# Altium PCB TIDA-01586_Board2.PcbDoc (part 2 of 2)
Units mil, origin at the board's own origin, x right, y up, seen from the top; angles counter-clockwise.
Board outline 2300 x 1600 mil, 4 copper layers (Layer 1 - Top Layer, Layer 2 - PWR, Layer 3 - GND, Layer 4 - Bottom Layer), stack 61.634 mil thick; 117 components, 50 nets, 280 pads, 152 vias.
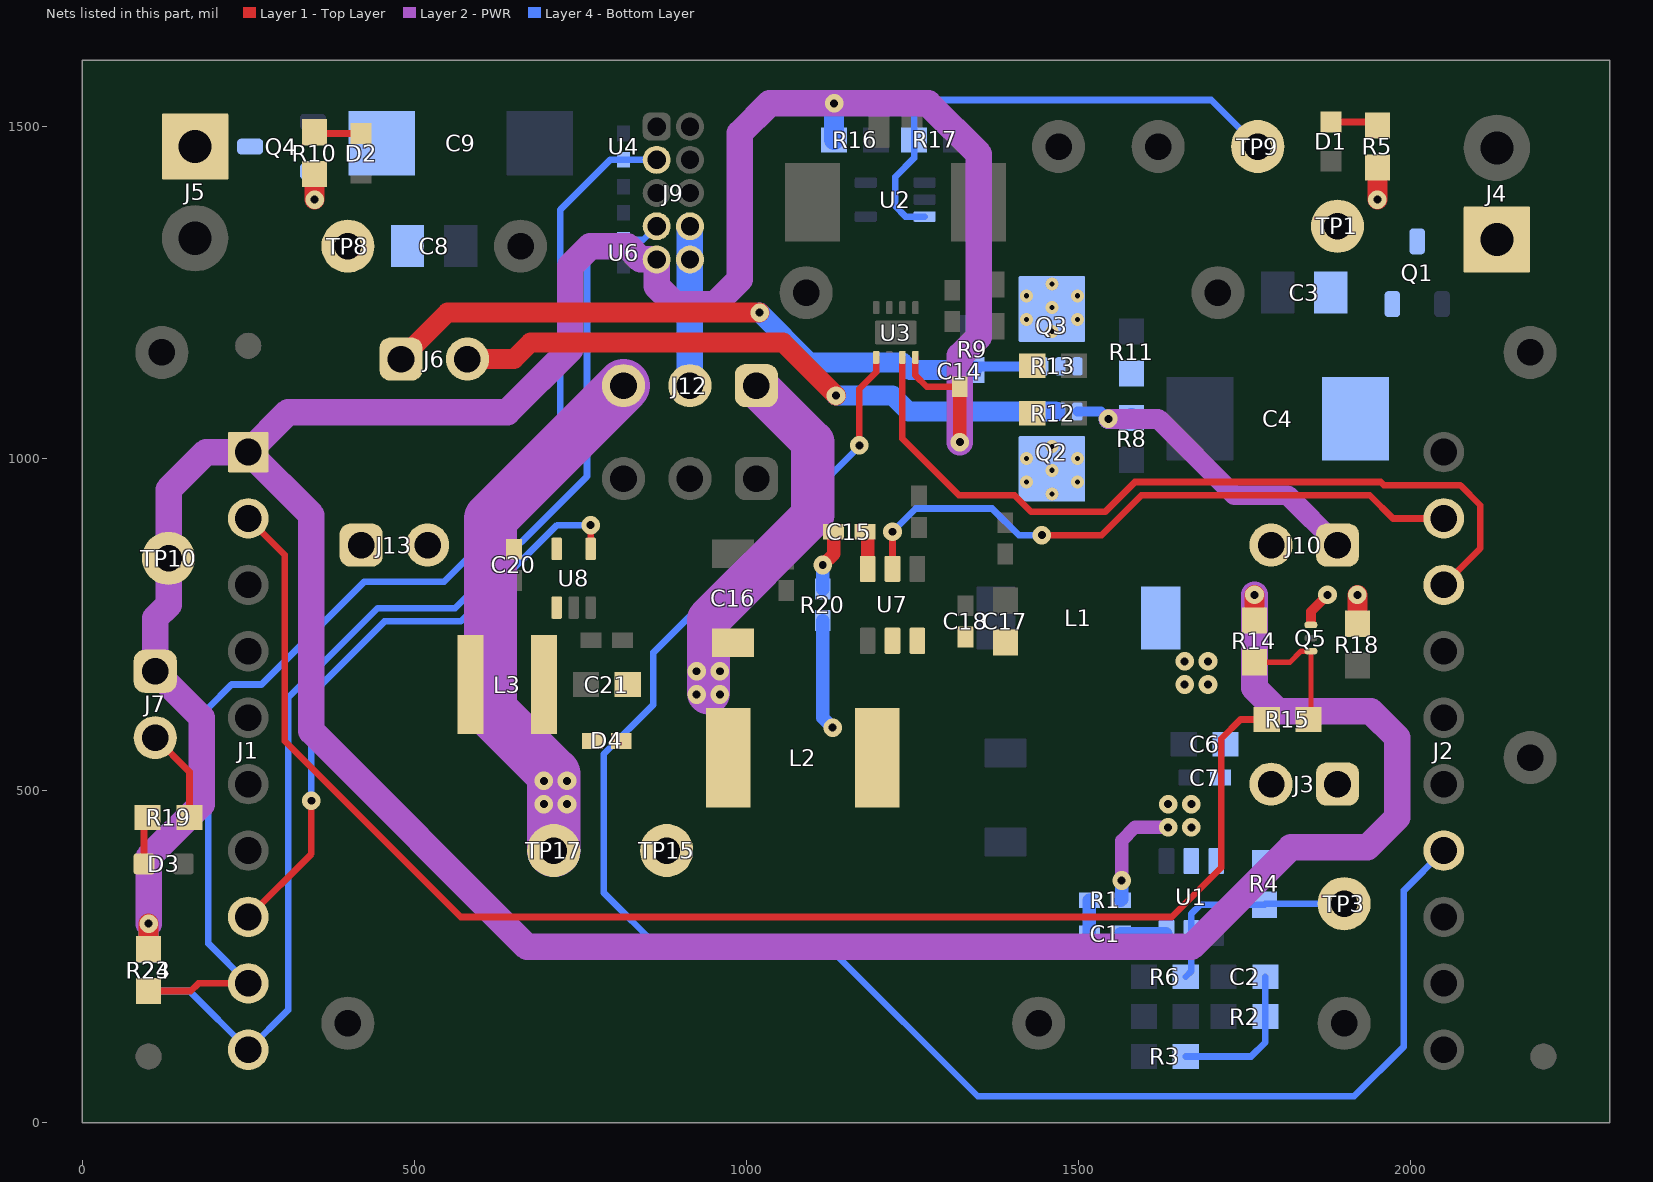
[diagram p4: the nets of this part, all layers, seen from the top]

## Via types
v1: diameter 28, hole 12, Layer 1 - Top Layer to Layer 4 - Bottom Layer, tented both sides, 136 vias
v2: diameter 19.68, hole 7.87, Layer 1 - Top Layer to Layer 4 - Bottom Layer, tented both sides, 16 vias

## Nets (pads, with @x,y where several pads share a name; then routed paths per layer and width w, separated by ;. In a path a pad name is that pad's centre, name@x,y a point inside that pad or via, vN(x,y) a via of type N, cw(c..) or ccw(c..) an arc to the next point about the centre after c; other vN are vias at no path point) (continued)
N12V_PRES: J1.2 R15.2 | length 2182.7
  Layer 1 - Top Layer w10: J1.2@250,910 305,855 305,575 570,310 1640.49,310 1715,384.51 1715,578.29 1743.94,607.24 R15.2@1783.5,607.24
N_SLEEP: J2.18 U3.7 | length 1214.1
  Layer 1 - Top Layer w10: U3.7@1234.84,1152.6 1234.84,1030.16 1320,945 1403.82,945 1428.82,920 1540,920 1585,965 1955,965 1960,960 2075,960 2105,930 2105,865 J2.18@2050,810
NetC1_1: C1.1 U1.6 | length 69.3
  Layer 4 - Bottom Layer w10: U1.6@1631.73,285 U1.6@1632.6,285.87
  Layer 4 - Bottom Layer w20: C1.1@1563.62,285 U1.6@1631.73,285
NetC1_2: C1.2 R1.1 | length 50
  Layer 4 - Bottom Layer w20: C1.2@1516.38,285 R1.1@1516.38,335
NetC2_1: C2.1 R2.1 R3.2 | length 227.4
  Layer 4 - Bottom Layer w10: R3.2@1661.5,100 1760,100 1781.5,121.5 R2.1@1781.5,160 C2.1@1781.5,220
NetC15_1: C15.1 U7.6 | length 57.5
  Layer 1 - Top Layer w20: C15.1@1178.62,890 1182.6,886.02 U7.6@1182.6,834.13
NetC15_2: C15.2 R20.1 | length 93.2
  Layer 1 - Top Layer w20: v1(1115,840) 1131.38,856.38 C15.2@1131.38,890
  Layer 4 - Bottom Layer w20: R20.1@1115,803.62 v1(1115,840)
NetD1_1: D1.1 R5.1 | length 72.2
  Layer 1 - Top Layer w10: D1.1@1880,1506.91 1944.59,1506.91 R5.1@1950,1501.5
NetD2_1: D2.1 R10.1 | length 70.8
  Layer 1 - Top Layer w10: R10.1@350,1491.5 351.97,1489.53 D2.1@420,1489.53
NetD3_1: D3.1 R19.1 | length 72.2
  Layer 1 - Top Layer w10: D3.1@93.09,390 93.09,454.59 R19.1@98.5,460
NetJ4_1: J4.1 Q1.3
NetJ5_1: J5.1 Q4.3
NetJ7_2: J7.2 R19.2 | length 141.3
  Layer 1 - Top Layer w10: J7.2@110,580 161.5,528.5 R19.2@161.5,460
NetQ2_5: Q2.5 Q2.6 Q2.7 Q2.8 Q2.9@1460,984.61 R12.1
  other v2: 1460,946.91 1421.61,964.72 1498.39,964.72 1460,982.54 1421.61,1000.35 1498.39,1000.35 1460,1018.17
NetQ3_1: Q3.1 Q3.2 Q3.3 R11.1
NetQ3_5: Q3.5 Q3.6 Q3.7 Q3.8 Q3.9@1460,1225.39 R13.2
  other v2: 1460,1191.83 1421.61,1209.65 1498.39,1209.65 1460,1227.46 1421.61,1245.28 1498.39,1245.28 1460,1263.09
NetQ5_3: Q5.3@1850,710.32 R14.1 R15.1 | length 196.5
  Layer 1 - Top Layer w8: R14.1@1765,693.5 1818.5,693.5 1835.32,710.32 Q5.3@1850,710.32 1850,610.74 R15.1@1846.5,607.24
NetR4_2: R4.2 R6.2 TP3.1 U1.5 | length 334.7
  Layer 4 - Bottom Layer w10: R6.2@1661.5,220 1670,228.5 U1.5@1670,285.87 1670,315 1683.5,328.5 R4.2@1780,328.5 1781.5,330 TP3.1@1900,330
NetR17_2: R17.2 TP9.1 U2.3 | length 755.8
  Layer 4 - Bottom Layer w10: U2.3@1268.39,1364.41 1239.69,1364.41 1224.09,1380 1224.09,1424.09 1252.6,1452.6 R17.2@1252.6,1480 1252.6,1517.6 1275,1540 1700,1540 TP9.1@1770,1470
OPEN_ICR: J2.14 U3.5 | length 2658.9
  Layer 1 - Top Layer w10: v1(1170,1020) 1170,1105 1195.47,1130.47 U3.5@1195.47,1152.6
  Layer 4 - Bottom Layer w10: v1(1170,1020) 1170,1018.28 860,708.28 860,630 785,555 785,346.72 871.72,260 1128.32,260 1348.32,40 1915,40 1990,115 1990,350 J2.14@2050,410
PWM_BOOST: J1.8 U8.4 | length 936.3
  Layer 1 - Top Layer w10: J1.8@250,310 345,405 v1(345,485) ; U8.4@765.59,864.29 v1(765.59,900)
  Layer 4 - Bottom Layer w10: v1(345,485) 345,645 455,755 570,755 715,900 v1(765.59,900)
PWM_BUCK: J2.19 U7.5 | length 956.3
  Layer 1 - Top Layer w10: U7.5@1220,834.13 v1(1220,890) ; v1(1445,885) 1535,885 1595,945 1938.62,945 1973.62,910 J2.19@2050,910
  Layer 4 - Bottom Layer w10: v1(1220,890) 1255,925 1370,925 1410,885 v1(1445,885)
SCL: J1.9 J9.3 R23.1 U4.1 | length 1851.7
  Layer 1 - Top Layer w10: R23.1@100,198.5 163.5,198.5 175,210 J1.9@250,210
  Layer 4 - Bottom Layer w10: J1.9@250,210 190,270 190,625 225,660 270,660 425,815 545,815 720,990 720,1375 795.32,1450.32 U4.1@815,1450.32 ; 800.32,1450 J9.3@865,1450
SDA: J1.10 J9.7 R24.1 U6.1 | length 1779
  Layer 4 - Bottom Layer w10: R24.1@100,198.5 161.5,198.5 J1.10@250,110 310,170 310,640 445,775 561.57,775 760,973.43 760,1295 794.68,1329.68 U6.1@815,1329.68 844.68,1329.68 J9.7@865,1350
sw_12v5v: L1.1 R1.2 U1.2 | length 168.9
  Layer 2 - PWR w20: v1(1565,365) 1565,425 1585,445 v1(1635,445)
  Layer 4 - Bottom Layer w20: R1.2@1563.62,335 1565,336.38 v1(1565,365)
  other v1: 1670,445 1635,480 1670,480 1660,660 1695,660 1660,695 1695,695
sw_led_boost: D4.2 L3.2 U8.1
sw_led_buck: L2.1 R20.2 U7.2 | length 167.6
  Layer 4 - Bottom Layer w20: R20.2@1115,756.38 1115,610 v1(1130,595)
VCC: J9.8 J9.10 J12.2 | length 240
  Layer 4 - Bottom Layer w40: J12.2@915,1110 J9.10@915,1300 J9.8@915,1350
VCC_3V: C14.1 J1.1 J7.1 J9.9 R14.2 R16.2 R23.2 R24.2 TP10.1 U3.8 | length 6130.6
  Layer 1 - Top Layer w10: U3.8@1254.53,1152.6 1254.53,1125.47 1271.67,1108.33 C14.1@1321.32,1108.33
  Layer 1 - Top Layer w20: v1(1321.32,1025) C14.1@1321.32,1108.33
  Layer 1 - Top Layer w30: R23.2@100,261.5 v1(100,300) ; R14.2@1765,756.5 v1(1765,795)
  Layer 2 - PWR w40: v1(100,300) 100,400 180,480 180,610 J7.1@110,680 110,760 130,780 TP10.1@130,850 130,953.5 186.5,1010 J1.1@250,1010 ; v1(1321.32,1025) 1321.32,1154.92 1350,1183.6 1350,1458.7 1273.7,1535 v1(1132.08,1535) 1035,1535 990,1490 990,1270 952.5,1232.5 892.5,1232.5 865,1260 J9.9@865,1300 840.9,1300 820.9,1320 765,1320 735,1290 735,1165 640,1070 310,1070 J1.1@250,1010 ; v1(1765,795) 1765,655 1800,620 1940,620 1980,580 1980,460 1935,415 1820,415 1670,265 670,265 345,590 345,915 J1.1@250,1010
  Layer 4 - Bottom Layer w30: R24.2@100,261.5 v1(100,300) ; R16.2@1132.08,1480 v1(1132.08,1535)
VIN_5V: C8.2 C9.1 J6.1 J13.1 Q3.4 Q4.2 R9.2 R10.2 TP8.1 | length 1047.2
  Layer 1 - Top Layer w30: v1(349.97,1390) R10.2@350,1428.5 ; J6.1@480,1150 550,1220 v1(1020,1220)
  Layer 4 - Bottom Layer w15: R9.2@1340,1133.5 1345.5,1139 1376,1139 Q3.4@1421.61,1138.98
  Layer 4 - Bottom Layer w30: v1(1020,1220) 1095,1145 1235,1145 1246.5,1133.5 R9.2@1340,1133.5
vin_5vor: J6.2 Q2.1 Q2.2 Q2.3 | length 938.4
  Layer 1 - Top Layer w30: J6.2@580,1150 650,1150 675,1175 1055,1175 v1(1135,1095)
  Layer 4 - Bottom Layer w30: v1(1135,1095) 1220,1095 1243.98,1071.02 Q2.1@1421.61,1071.02 Q2.3@1465,1071.02
VIN_12V: C3.1 C4.1 J3.1 J10.1 Q1.2 Q2.4 Q5.1@1850,749.68 R5.2 R8.2 R18.1 TP1.1 | length 654.9
  Layer 1 - Top Layer w15: Q5.1@1850,753 1850,770 v1(1875,795)
  Layer 1 - Top Layer w30: R18.1@1920,751.5 v1(1920,795) ; v1(1950,1390) R5.2@1950,1438.5
  Layer 2 - PWR w30: v1(1545,1060) 1620,1060 1735,945 1815,945 J10.1@1890,870
  Layer 4 - Bottom Layer w15: Q2.4@1498.39,1071.02 1533.98,1071.02 v1(1545,1060)
  Layer 4 - Bottom Layer w30: v1(1545,1060) 1578.5,1060 R8.2@1580,1061.5
vin_12v5v: C6.1 C7.1 J3.2 R4.1 U1.3
vin_led_boost: C20.1 J13.2 L3.1 U8.5
vin_led_buck: C17.1 C18.1 J10.2 U7.3
vled_top_boost: C21.1 D4.1 J12.3 TP17.1 | length 822.2
  Layer 2 - PWR w80: TP17.1@710,410 710,525 615,620 615,910 J12.3@815,1110
  other v1: 695,480 730,480 695,515 730,515
vled_top_buck: C16.1 J12.1 L2.2 TP15.1 | length 563.2
  Layer 2 - PWR w65: 943,647 943,758 1100,915 1100,1025 J12.1@1015,1110
  other v1: 925,645 960,645 925,680 960,680
pads on no net: D3. FID1.1 FID2.1 FID3.1 FID4.1 FID5.1 FID6.1 J1.3 J1.4 J1.6 J1.7 J2.11 J2.12 J2.13 J2.16 J2.17 J8.3 J8.4 Q2.9@1421.61,963.74 Q2.9@1433.92,982.54 Q2.9@1433.92,1018.17 Q2.9@1447.2,963.74 Q2.9@1460,997.11 Q2.9@1472.8,963.74 Q2.9@1486.08,982.54 Q2.9@1486.08,1018.17 Q2.9@1498.39,963.74 Q3.9@1421.61,1246.26 Q3.9@1433.92,1191.83 Q3.9@1433.92,1227.46 Q3.9@1447.2,1246.26 Q3.9@1460,1212.89 Q3.9@1472.8,1246.26 Q3.9@1486.08,1191.83 Q3.9@1486.08,1227.46 Q3.9@1498.39,1246.26 Q5.1@1850,750.67 Q5.2@1850,730 Q5.3@1850,709.33 SH-J3.0 SH-J6.0 SH-J7.0 SH-J10.0 SH-J11.0 SH-J12.0 SH-J13.0 U2.4 U3.9@1207.28,1190 U3.9@1242.72,1190

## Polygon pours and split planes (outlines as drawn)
GND on Layer 3 - GND "Layer 3 - GND - GND " (solid, remove dead copper, pour order 0): 20,20 2280,20 2280,1580 20,1580
GND on Layer 1 - Top Layer "Layer 1 - Top Layer - GND " (solid, remove dead copper, pour order 4): 20,20 2280,20 2280,1580 20,1580
GND on Layer 2 - PWR "Layer 2 - PWR - GND " (solid, remove dead copper, pour order 6): 20,20 2280,20 2280,1580 20,1580
GND on Layer 4 - Bottom Layer "Layer 4 - Bottom Layer - GND " (solid, remove dead copper, pour order 8): 20,20 2280,20 2280,1580 20,1580

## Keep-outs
Keep-Out Layer:
  text ".Layer_Name" at 577,-858.49 h60

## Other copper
Layer 1 - Top Layer:
  region net GND: 1201,1238 1201,1214 1207,1208 1283,1208 1298,1223 1385,1223 1389,1219 1389,1169 1359,1139 1301,1139 1268,1172 1163,1172 1150,1185 1150,1225 1163,1238
  region net fb_led_buck: 1075,832 1075,980 1050,1005 985,1005 965,985 965,935 935,905 935,832
  region net vled_top_boost: 795,680 795,615 795,550 780,535 695,535 650,490 650,380 665,365 775,365 795,385 795,425 885,515 885,660 865,680
  region net DRV_5V: 1249,1217 1277,1217 1295,1235 1385,1235 1390,1240 1390,1280 1385,1285 1305,1285 1275,1255 1258,1255 1249,1246
  region net NetQ3_5: 1455,1118.39 1455,1163.39 1475,1183.39 1500,1183.39 1510,1193.39 1510,1261.39 1496.39,1275 1435,1275 1410,1250 1410,1118.39
  region net NetQ2_5: 1455,1090 1455,1045 1475,1025 1500,1025 1510,1015 1510,947 1500,937 1435,937 1410,962 1410,1090
  region net vin_led_boost: 610,831 626,847 722,847 730,855 730,895 715,910 510,910 480,880 480,585 500,565 590,565 610,585
  region net GND: 660,795 670,805 721,805 732,794 732,618 745,605 767,605 784,622 784,738 778,744 756,744 748,752 748,819 733,834 635,834 630,829 630,800 635,795
  region net sw_led_boost: 737,590 723,604 723,791 721,793 688,793 650,755 650,590 685,555 782,555 785,558 785,587 782,590
  region net vled_top_buck: 1005,755 1020,740 1020,420 960,360 840,360 815,385 815,420 900,505 900,740 915,755
  region net sw_led_buck: 1233,745 1233,473 1205,445 1145,445 1115,475 1115,604.34 1207,696.34 1207,745 1212,750 1228,750
  region net GND: 1420,855 1400,875 1370,875 1345,900 1320,900 1285,865 1285,810 1275,800 1105,800 1085,820 1045,820 1035,810 1035,705 1050,690.22 1179.78,690.22 1194.57,705 1194.57,749.57 1207,762 1420,762
  region net vin_led_buck: 1825,850 1805,830 1660,830 1485,655 1275,655 1245,685 1245,745 1250,750 1435,750 1605,920 1805,920 1825,900
  pour cut-out: 1199.17,420.08 1222.8,443.7 1222.8,690.22 947.2,690.22 947.2,443.7 970.83,420.08
  pour cut-out: 618.35,577.32 661.65,577.32 661.65,742.68 618.35,742.68
  text ".Layer_Name" at 577,-858.49 h60
Layer 2 - PWR:
  region net sw_12v5v: 1620,485 1640,505 1640,620 1640,700 1650,710 1710,710 1720,700 1720,440 1705,425 1635,425 1620,440
  text ".Layer_Name" at 577,-858.49 h60
Layer 3 - GND:
  text ".Layer_Name" at 577,-858.49 h60
Layer 4 - Bottom Layer:
  region net vin_5vor: 1464,1086 1481,1086 1481,1056 1464,1056
  region net NetQ3_1: 1439,1122 1456,1105 1600,1105 1600,1150 1595,1155 1443,1155 1439,1151
  region net 5v_buck: 1415,815 1430,800 1430,530 1405,505 1355,505 1325,475 1325,385 1505,205 1505,140 1525,120 1620,120 1620,80 1376.79,80 1170,286.79 1170,631 1354,815
  region net sw_12v5v: 1585,690 1630,645 1705,645 1720,660 1720,750 1655,815 1600,815 1585,800
  region net sw_12v5v: 1685,485 1675,495 1630,495 1620,485 1620,440 1630,430 1646,430 1657,419 1657,374 1685,374
  region net vin_12v5v: 1825,585 1815,595 1705,595 1695,585 1695,375 1705,365 1815,365 1825,375
  region net VIN_12V: 1985,495 1965,475 1860,475 1840,495 1840,1385 1860,1405 1965,1405 1985,1385
  region net NetJ4_1: 1998,1366 2017,1385 2185,1385 2185,1275 2015,1275 1998,1292
  region net VIN_5V: 380,1460 390.87,1470.87 390.87,1520.87 400,1530 500,1530 520,1510 520,970 460,910 460,845 450,835 345,835 320,860 320,1450 330,1460
  region net NetJ5_1: 110,1530 250,1530 280,1500 280,1440 250,1410 110,1410
  pour cut-out: 1350.39,630.08 1370.08,610.39 1629.92,610.39 1649.61,630.08 1649.61,889.92 1629.92,909.61 1370.08,909.61 1350.39,889.92
  text ".Layer_Name" at 577,-858.49 h60

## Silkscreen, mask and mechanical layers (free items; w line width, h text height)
Top Overlay:
  text "ICR +" at 1430,1540 h50
  text "LDO_EN" at 1685,1540 h50
  text "DRV_5V" at 1535,1370 h50
  text "VIN_12V" at 1800,1250 h50
  text "ICR -" at 927,1228 h50
  text "VIN_5V" at 300,1220 h50
  text "VCC_3V" at 60,780 h50 r90
  text "Vled_Boost" at 620,480 h50
  text "Buck_EN" at 1640,320 h50 r359.97
  text "Vled_Buck" at 775,315 h50
  text "5V_Buck" at 1360,225 h50
  text ".Layer_Name" at 577,-858.49 h60
Bottom Overlay:
  rectangle: 771.68,24.75 1071.68,124.75
  text "'.TID' .PCB_Rev-" at 1310,170 h80
  text ".Layer_Name" at 577,-858.49 h60
Top Paste:
  text ".Layer_Name" at 577,-858.49 h60
Bottom Paste:
  text ".Layer_Name" at 577,-858.49 h60
Top Solder:
  text ".Layer_Name" at 577,-858.49 h60
  text ".Layer_Name" at 577,-858.49 h60
Bottom Solder:
  text ".Layer_Name" at 577,-858.49 h60
Drill Guide:
  text ".Layer_Name" at 577,-858.49 h60
M1 Board Outline:
  the board outline again, w10
  text ".Layer_Name" at 577,-858.49 h60
M2 Board Dimensions:
  rectangle: 0,-275 125,-150
  rectangle: 125,-400 500,-275
  lines w7: 0,-275 1000,-275 ; 125,-400 125,-150 ; 250,-400 250,-150 ; 500,-400 500,-150 ; 750,-400 750,-150 ; 0,-400 1000,-400 1000,-150 0,-150 0,-400
  text ".Layer_Name" at 577,-858.49 h60
M3 3D STEP Top:
  text ".Layer_Name" at 577,-858.49 h60
M4 3D STEP Bottom:
  text ".Layer_Name" at 577,-858.49 h60
M5 Assembly Top:
  lines w10: -292,-930.17 6308,-930.17 ; -292,-726.83 6310,-726.83 ; -292,-523.5 -292,-1133.5 3713,-1133.5 6310,-1133.5 6310,-523.5 -291.5,-523.5 -291.5,-1133.5 1284,-1133.5 ; 2173,-1133.5 2173,-523.5 ; 3440,-726.83 3440,-523.5 ; 4280,-726.83 4280,-523.5 ; 4902,-1140 4902,-937.17
  text "COMPONENTS MARKED 'DNP' SHOULD NOT BE POPULATED." at 1153.5,-318.5 h60
  text "ASSEMBLY VARIANT:" at 1153,-434 h60
  text ".VariantName" at 2189,-434 h60
  text "PCB VIEWED FROM TOP SIDE" at -228.5,-655.67 h60
  text "BOARD #:" at 2248,-655.67 h60
  text ".PRJ_Number" at 2793.5,-655.67 h60
  text "REV:" at 3638,-655.67 h60
  text ".PCB_Rev" at 3929.5,-655.67 h60
  text "SVN REV:" at 4476,-655.67 h60
  text ".VersionControl_RevNumber" at 4982,-655.67 h60
  text "TID #:" at 2248,-859 h60
  text ".TID" at 2793.5,-859 h60
  text "PLOT NAME =" at -228.5,-1064.34 h60
  text ".plot_File_Name" at 577,-1064.34 h60
  text "GENERATED    :" at 2250,-1064.34 h60
  text ".Print_Date" at 3119.5,-1064.34 h60
  text ".Print_Time" at 3848.5,-1064.34 h60
  text "TEXAS INSTRUMENTS" at 5113,-1064.34 h60
M6 Assembly Bottom:
  lines w10: -292.5,-727.33 6309.5,-727.33 ; -290.5,-930.67 6309.5,-930.67 ; 1115.5,-1140.5 1115.5,-937.67 ; 1737.5,-727.33 1737.5,-524 ; 2577.5,-727.33 2577.5,-524 ; 3844.5,-1134 3844.5,-524 ; 4733.5,-1134 6309,-1134 6309,-524 -292.5,-524 -292.5,-1134 2304.5,-1134 6309.5,-1134 6309.5,-524
  text "COMPONENTS MARKED 'DNP' SHOULD NOT BE POPULATED." at 6102,-318 h60
  text ".VariantName" at 5058,-434 h60
  text "ASSEMBLY VARIANT:" at 6097,-434 h60
  text ".VersionControl_RevNumber" at 1035.5,-656.17 h60
  text "SVN REV:" at 1541.5,-656.17 h60
  text ".PCB_Rev" at 2088,-656.17 h60
  text "REV:" at 2379.5,-656.17 h60
  text ".PRJ_Number" at 3224,-656.17 h60
  text "BOARD #:" at 3769.5,-656.17 h60
  text "PCB VIEWED FROM BOTTOM SIDE" at 6246,-656.17 h60
  text ".TID" at 3224,-859.5 h60
  text "TID #:" at 3769.5,-859.5 h60
  text "TEXAS INSTRUMENTS" at 904.5,-1064.84 h60
  text ".Print_Time" at 2169,-1064.84 h60
  text ".Print_Date" at 2898,-1064.84 h60
  text "GENERATED    :" at 3767.5,-1064.84 h60
  text ".plot_File_Name" at 5440.5,-1064.84 h60
  text "PLOT NAME =" at 6246,-1064.84 h60
M9 Title Sheet:
  drawing of 1178 lines, arcs and shapes, not listed
  text "1" at 739.84,8036.5 h70
  text "2" at 3235.5,8036.5 h70
  text "3" at 5724.84,8036.5 h70
  text "4" at 8231.51,8036.5 h70
  text "5" at 10730.5,8036.5 h70
  text "6" at 13235.5,8036.5 h70
  text "A" at -416.5,6893.5 h70
  text "A" at 14383.5,6893.5 h70
  text "B" at -416.5,4513.5 h70
  text "B" at 14383.5,4513.5 h70
  text "C" at -416.5,2138.5 h70
  text "C" at 14383.5,2138.5 h70
  text "PROJECT TITLE:" at 11343.5,277.5 h45
  text ".PRJ_Title" at 11393.5,144.17 h70
  text "DESIGNED FOR:" at 11343.5,-23.5 h45
  text ".PRJ_Customer" at 11393.5,-163.5 h70
  text "D" at -416.5,-231.5 h70
  text "D" at 14383.5,-231.5 h70
  text "FILE NAME:" at 11343.5,-323.5 h45
  text ".PCB_File_Name_No_Path" at 11393.5,-443.5 h70
  text "Texas Instruments (TI) and/or its licensors do not warrant the accuracy or completeness of this specification" at 6374,-605.34 h45
  text "ENGINEER:" at 11343.5,-613.5 h45
  text "LAYOUT BY:" at 12848.5,-613.5 h45
  text "or any information contained therein. TI and/or its licensors do not warrant that this design will meet" at 6329.01,-718 h45
  text ".PRJ_Engineer" at 11393.5,-768.49 h70
  text "JMM" at 12852,-800 h100
  text "s  o  l  u  t  i  o  n  s" at 13710,-803 h68
  text "the specifications, will be suitable for your application or fit for any particular purpose, or will operate in" at 6329.01,-830.67 h45
  text ".Layer_Name" at 577,-858.49 h60
  text "ALTIUM DESIGNER VERSION:" at 12848.5,-923.5 h45
  text "an implementation. TI and/or its licensors do not warrant that the design is production worthy. You should" at 6329.01,-943.33 h45
  text "completely validate and test your design implementation to confirm the system functionality for your application." at 6374,-1056 h45
  text ".print_Scale" at 11393.5,-1056.83 h70
  text ".Application_BuildNumber" at 12899,-1056.83 h70
  text "1" at 739.84,-1263.5 h70
  text "2" at 3235.5,-1263.5 h70
  text "3" at 5724.84,-1263.5 h70
  text "4" at 8231.51,-1263.5 h70
  text "5" at 10730.5,-1263.5 h70
  text "6" at 13235.5,-1263.5 h70
M10 Fab Notes:
  drawing of 189 lines, arcs and shapes, not listed
  text "DESIGN INFORMATION" at 12382.02,6356.17 h60
  text "MIN. TRACK WIDTH:" at 11737.46,6224.05 h60
  text "8" at 12833.7,6224.05 h60
  text "MIL" at 12988.46,6224.05 h60
  text "MIN. CLEARANCE:" at 11737.46,6099.92 h60
  text "0.2" at 12773.7,6099.93 h60
  text "mm" at 12988.46,6099.92 h60
  text "MIN. VIA PAD SIZE:" at 11737.46,5975.8 h60
  text "20" at 12803.71,5975.8 h60
  text "MIL" at 12988.46,5975.8 h60
  text "0.05mm (2MIL)" at 12432.46,5845.9 h60
  text "MINIMUM ANNULAR RING" at 11408.23,5837.67 h60
  text "EXTERNAL" at 13140.46,5837.67 h60
  text "PER" at 11608.23,5727.55 h60
  text "IPC-D-275 CLASS 2 LEVEL C" at 11828.23,5727.54 h60
  text "MIL, HOLES" at 13316.46,5627.07 h60
  text "+/-" at 12924,5618.48 h60
  text "+/-" at 13778,5618.48 h60
  text "REGISTRATION TOLERANCES:" at 11408.23,5617.42 h60
  text "METAL" at 12608,5617.42 h60
  text "5" at 13184.2,5617.42 h60
  text "3" at 14017.2,5617.42 h60
  text "MIL" at 14133.46,5617.42 h60
  text "HOLE SIZE TOLERANCE (UNLESS OTHERWISE SPECIFIED):" at 11408.23,5519.1 h60
  text "+/-" at 13778,5516.23 h60
  text "3" at 14017.2,5515.17 h60
  text "MIL" at 14133.46,5515.17 h60
  text "MATERIAL:" at 11333.46,5377.52 h60
  text "FR-4 High Tg" at 12319.9,5249 h60
  text "X" at 12175.46,5241.01 h60
  text "FR-408" at 11754.46,5236.49 h60
  text "OTHER" at 13242.46,5236.49 h60
  text "62 MIL (1.6mm) +/-10%" at 12074.56,5093.46 h60
  text "X" at 11954.46,5091.01 h60
  text "THICKNESS:" at 11408.23,5085.24 h60
  text "OTHER" at 13359.46,5085.24 h60
  text "TOLERANCE:" at 11408.23,4946.92 h60
  text "X" at 12256.46,4946.92 h60
  text "ANSI IPC-6012 TYPE 3 CLASS 2" at 12434.48,4946.92 h60
  text "OTHER +/-" at 12434.46,4802.73 h60
  text "BOW & TWIST:" at 11408.23,4657.54 h60
  text "X" at 12256.46,4657.54 h60
  text "ANSI IPC-6012 TYPE 3 CLASS 2" at 12434.48,4657.54 h60
  text "OTHER +/-" at 12434.46,4510.85 h60
  text "DRILLING:" at 11333.46,4380.23 h60
  text "NC_DRILL FILES" at 13094.46,4275.04 h60
  text "REFERENCE:" at 11408.23,4271.1 h60
  text "X" at 12065.46,4271.01 h60
  text "AS SHOWN" at 12243.46,4271.1 h60
  text "X" at 12966.46,4271.1 h60
  text "OTHER" at 13392.46,4128.85 h60
  text "PTH COPPER THICKNESS:" at 11407.91,4125.32 h60
  text "X" at 12547.14,4125.32 h60
  text "20-30 um" at 12675.14,4125.32 h60
  text "BOARD FINISH:" at 11333.46,3977.73 h60
  text "SILKSCREEN:" at 11488.68,3867.6 h60
  text "X" at 12446.46,3867.6 h60
  text "TOP" at 12563.46,3867.6 h60
  text "X" at 12956.46,3867.6 h60
  text "BOTTOM" at 13074.46,3867.6 h60
  text "SILKSCREEN COLOR:" at 11488.68,3712.41 h60
  text "X" at 12445.46,3712.41 h60
  text "WHITE" at 12563.46,3712.41 h60
  text "OTHER" at 13074.46,3712.41 h60
  text "GREEN" at 12694.46,3568.96 h60
  text "OTHER" at 13312.46,3568.96 h60
  text "X" at 13161.46,3567.6 h60
  text "Red" at 13686.46,3567.6 h60
  text "SOLDER RESIST COLOR:" at 11488.68,3562.1 h60
  text "X" at 12576.46,3414.71 h60
  text "MATTE" at 12694.46,3414.71 h60
  text "SEMI-GLOSS" at 13312,3414.07 h60
  text "IMMERSION GOLD (ENIG)" at 12394.46,3241.94 h60
  text "ENEPIG" at 13732,3234.72 h60
  text "SURFACE FINISH:" at 11333.46,3233.72 h60
  text "X" at 12216.46,3233.72 h60
  text "IMM. TIN/SILVER OR EQUIV" at 11663,3096.4 h60
  text "OTHER" at 13094.46,3092.47 h60
  text "ARRAY/PANEL:" at 11333.46,2937.09 h60
  text "CUT AND TRIM PER M1 BOARD OUTLINE" at 12394.46,2928.87 h60
  text "N.C. ROUTE" at 12394.46,2792.9 h60
  text "X" at 13082.46,2792.9 h60
  text "V. SCORE" at 13260.46,2792.9 h60
  text "CERTIFICATION:" at 11333.46,2663.77 h60
  text "MATERIALS AND WORKMANSHIP FOR ALL PCBS" at 12058.46,2663.77 h60
  text "TO MEET OR EXCEED THE REQUIREMENTS OF:" at 12058.46,2569.71 h60
  text "X" at 11695.97,2441.08 h60
  text "ANSI IPC-A-600F CLASS ->" at 11823.96,2441.08 h60
  text "X" at 13471.97,2441.08 h60
  text "2" at 13581.96,2441.08 h60
  text "1" at 13266.96,2439.58 h60
  text "3" at 13935.96,2439.58 h60
  text "X" at 12507.97,2293.39 h60
  text "RoHS" at 12635.96,2293.39 h60
  text "OTHER" at 13280.36,2293.39 h60
  text "PER ORDER" at 13677.42,2293.39 h60
  text "ALL BOARDS MUST MEET OR EXCEED UL94-V0 REQUIREMENTS." at 11361,2139.57 h60
  text "PCB MUST BEAR THE UL94V-0 UL REGISTERED MATERIAL ID NUMBER" at 11361,2023.5 h60
  text "ADDITIONAL REQUIREMENTS:" at 11333.46,1854.08 h60
  text "MICROSECTION:" at 11408.23,1746.95 h60
  text "YES" at 12313.96,1746.95 h60
  text "REQUIRED" at 13175.46,1602.62 h60
  text "BARE BOARD ELEC. TEST:" at 11408.23,1599.76 h60
  text "NONE" at 12713.96,1599.76 h60
  text "X" at 13057.46,1599.76 h60
  text "PER ORDER" at 13767.46,1599.76 h60
  text "XX MIL VIAS REQUIRE NON-CONDUCTIVE FILL AND PLANARIZE" at 11576.38,1394.82 h59
  text "XX MIL VIAS REQUIRE CONDUCTIVE FILL AND PLANARIZE" at 11584.38,1290.84 h60
  text "OUTER XX MIL TRACES REQUIRE 50 OHM SINGLE-ENDED IMPEDANCE" at 11583.39,1127.46 h58
  text "LAYER 2 & 3 (INNER LAYERS) XX MIL WIDE, XX MIL SPACE / TRACES REQUIRE 100 OHM DIFFERENTIAL IMPEDANCE" at 11575.39,891.74 h60
  text ".Layer_Name" at 577,-858.49 h60
M11 Gerber Information:
  lines w10: -292,-930.17 6308,-930.17 ; -292,-726.83 6310,-726.83 ; -292,-523.5 -292,-1133.5 3713,-1133.5 6310,-1133.5 6310,-523.5 -291.5,-523.5 -291.5,-1133.5 1284,-1133.5 ; 2173,-1133.5 2173,-523.5 ; 3440,-726.83 3440,-523.5 ; 4280,-726.83 4280,-523.5 ; 4902,-1140 4902,-937.17
  text "ALL ARTWORK VIEWED FROM TOP SIDE" at -228.5,-655.67 h60
  text "BOARD #:" at 2248,-655.67 h60
  text ".PRJ_Number" at 2793.5,-655.67 h60
  text "REV:" at 3638,-655.67 h60
  text ".PCB_Rev" at 3929.5,-655.67 h60
  text "SVN REV:" at 4476,-655.67 h60
  text ".VersionControl_RevNumber" at 4982,-655.67 h60
  text "LAYER NAME =" at -228.5,-858.49 h60
  text "TID #:" at 2248,-859 h60
  text ".TID" at 2793.5,-859 h60
  text "PLOT NAME =" at -228.5,-1064.34 h60
  text ".plot_File_Name" at 577,-1064.34 h60
  text "GENERATED    :" at 2250,-1064.34 h60
  text ".Print_Date" at 3119.5,-1064.34 h60
  text ".Print_Time" at 3848.5,-1064.34 h60
  text "TEXAS INSTRUMENTS" at 5113,-1064.34 h60
M12 Stackup:
  drawing of 295 lines, arcs and shapes, not listed
  text "Layer" at 9312.5,7842.5 h60
  text "Name" at 9722.41,7842.5 h60
  text "Material" at 11132,7842.5 h60
  text "Thickness" at 11991.77,7842.5 h60
  text "Constant" at 12641.6,7842.5 h60
  text "Board Layer Stack" at 13211.47,7842.5 h60
  text "1" at 9312.5,7722.5 h60
  text "Top Overlay" at 9722.41,7722.5 h60
  text "2" at 9312.5,7602.5 h60
  text "Top Solder" at 9722.41,7602.5 h60
  text "Solder Resist" at 11132,7602.5 h60
  text "0.40mil" at 11991.77,7602.5 h60
  text "3.5" at 12641.6,7602.5 h60
  text "3" at 9312.5,7482.5 h60
  text "Layer 1 - Top Layer" at 9722.41,7482.5 h60
  text "Copper" at 11132,7482.5 h60
  text "1.40mil" at 11991.77,7482.5 h60
  text "4" at 9312.5,7362.5 h60
  text "Dielectric 1" at 9722.41,7362.5 h60
  text "FR-4" at 11132,7362.5 h60
  text "7.00mil" at 11991.77,7362.5 h60
  text "4.2" at 12641.6,7362.5 h60
  text "5" at 9312.5,7242.5 h60
  text "Layer 2 - PWR" at 9722.41,7242.5 h60
  text "Copper" at 11132,7242.5 h60
  text "1.42mil" at 11991.77,7242.5 h60
  text "6" at 9312.5,7122.5 h60
  text "Dielectric 2" at 9722.41,7122.5 h60
  text "FR-4" at 11132,7122.5 h60
  text "42.00mil" at 11991.77,7122.5 h60
  text "4.8" at 12641.6,7122.5 h60
  text "7" at 9312.5,7002.5 h60
  text "Layer 3 - GND" at 9722.41,7002.5 h60
  text "Copper" at 11132,7002.5 h60
  text "1.42mil" at 11991.77,7002.5 h60
  text "8" at 9312.5,6882.5 h60
  text "Dielectric 3" at 9722.41,6882.5 h60
  text "FR-4" at 11132,6882.5 h60
  text "7.00mil" at 11991.77,6882.5 h60
  text "4.2" at 12641.6,6882.5 h60
  text "9" at 9312.5,6762.5 h60
  text "Layer 4 - Bottom Layer" at 9722.41,6762.5 h60
  text "Copper" at 11132,6762.5 h60
  text "1.40mil" at 11991.77,6762.5 h60
  text "10" at 9312.5,6642.5 h60
  text "Bottom Solder" at 9722.41,6642.5 h60
  text "Solder Resist" at 11132,6642.5 h60
  text "0.40mil" at 11991.77,6642.5 h60
  text "3.5" at 12641.6,6642.5 h60
  text "11" at 9312.5,6522.5 h60
  text "Bottom Overlay" at 9722.41,6522.5 h60
  text ".Layer_Name" at 577,-858.49 h60
M13 Component Bodies Top:
  text ".Layer_Name" at 577,-858.49 h60
M14 Component Bodies Bottom:
  text ".Layer_Name" at 577,-858.49 h60
M15 Courtyards Top:
  text ".Layer_Name" at 577,-858.49 h60
M16 Courtyards Bottom:
  text ".Layer_Name" at 577,-858.49 h60
Drill Drawing:
  circle w10: c3073.72,229.68 r27.63
  lines w10: 3046.09,381.63 3101.34,381.63 3073.72,326.38 3046.09,381.63 ; 3046.09,450.7 3101.34,450.7 3101.34,505.95 3046.09,505.95 3046.09,450.7 ; 3046.09,588.83 3059.9,588.83 3073.72,575.02 3087.53,588.83 3101.34,588.83 3087.53,602.64 3101.34,616.46 3087.53,616.46 3073.72,630.27 3059.9,616.46 3046.09,616.46 3059.9,602.64 3046.09,588.83 ; 3046.09,726.96 3073.72,699.34 3101.34,726.96 3073.72,754.59 3046.09,726.96 ; 3046.09,823.66 3073.72,837.47 3101.34,823.66 3087.53,851.28 3101.34,878.91 3073.72,865.1 3046.09,878.91 3059.9,851.28 3046.09,823.66
  lines w12: 2996,164.76 6696.13,164.76 ; 2996,910.68 6696.13,910.68 ; 3333.86,40.44 3333.86,1035 ; 3665.86,40.44 3665.86,1035 ; 4302.43,40.44 4302.43,1035 ; 4561.57,40.44 4561.57,1035 ; 4936.72,40.44 4936.72,1035 ; 6129.7,40.44 6129.7,1035 ; 2996,40.44 6696.13,40.44 6696.13,1035 2996,1035 2996,40.44
  text "Symbol" at 3070.59,947.98 h72
  text "Quantity" at 3371.16,947.98 h72
  text "Finished Hole Size" at 3703.16,947.98 h72
  text "Plated" at 4339.72,947.98 h72
  text "Hole Type" at 4598.86,947.98 h72
  text "Drill Layer Pair" at 4974.02,947.98 h72
  text "Hole Tolerance" at 6166.99,947.98 h72
  text "16" at 3371.16,823.66 h60
  text "7.87mil (0.200mm)" at 3703.16,823.66 h60
  text "PTH" at 4339.72,823.66 h60
  text "Round" at 4598.86,823.66 h60
  text "Layer 1 - Top Layer - Layer 4 - Bottom Layer" at 4974.02,823.66 h60
  text "136" at 3371.16,699.34 h60
  text "12.00mil (0.305mm)" at 3703.16,699.34 h60
  text "PTH" at 4339.72,699.34 h60
  text "Round" at 4598.86,699.34 h60
  text "Layer 1 - Top Layer - Layer 4 - Bottom Layer" at 4974.02,699.34 h60
  text "10" at 3371.16,575.02 h60
  text "27.56mil (0.700mm)" at 3703.16,575.02 h60
  text "PTH" at 4339.72,575.02 h60
  text "Round" at 4598.86,575.02 h60
  text "Layer 1 - Top Layer - Layer 4 - Bottom Layer" at 4974.02,575.02 h60
  text "34" at 3371.16,450.7 h60
  text "40.00mil (1.016mm)" at 3703.16,450.7 h60
  text "PTH" at 4339.72,450.7 h60
  text "Round" at 4598.86,450.7 h60
  text "Layer 1 - Top Layer - Layer 4 - Bottom Layer" at 4974.02,450.7 h60
  text "20" at 3371.16,326.38 h60
  text "40.16mil (1.020mm)" at 3703.16,326.38 h60
  text "PTH" at 4339.72,326.38 h60
  text "Round" at 4598.86,326.38 h60
  text "Layer 1 - Top Layer - Layer 4 - Bottom Layer" at 4974.02,326.38 h60
  text "4" at 3371.16,202.06 h60
  text "50.00mil (1.270mm)" at 3703.16,202.06 h60
  text "PTH" at 4339.72,202.06 h60
  text "Round" at 4598.86,202.06 h60
  text "Layer 1 - Top Layer - Layer 4 - Bottom Layer" at 4974.02,202.06 h60
  text "220 Total" at 3371.16,77.74 h60
  text ".Layer_Name" at 577,-858.49 h60
M17 Embedded Cavity:
  text ".Layer_Name" at 577,-858.49 h60
M18 Embedded Assembly:
  text ".Layer_Name" at 577,-858.49 h60
M19 Embedded Keepout:
  text ".Layer_Name" at 577,-858.49 h60

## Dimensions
0,0 to 2300,0 on M2 Board Dimensions
0,0 to 0,1600 on M2 Board Dimensions
0,-400 to 1000,-400 on M2 Board Dimensions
